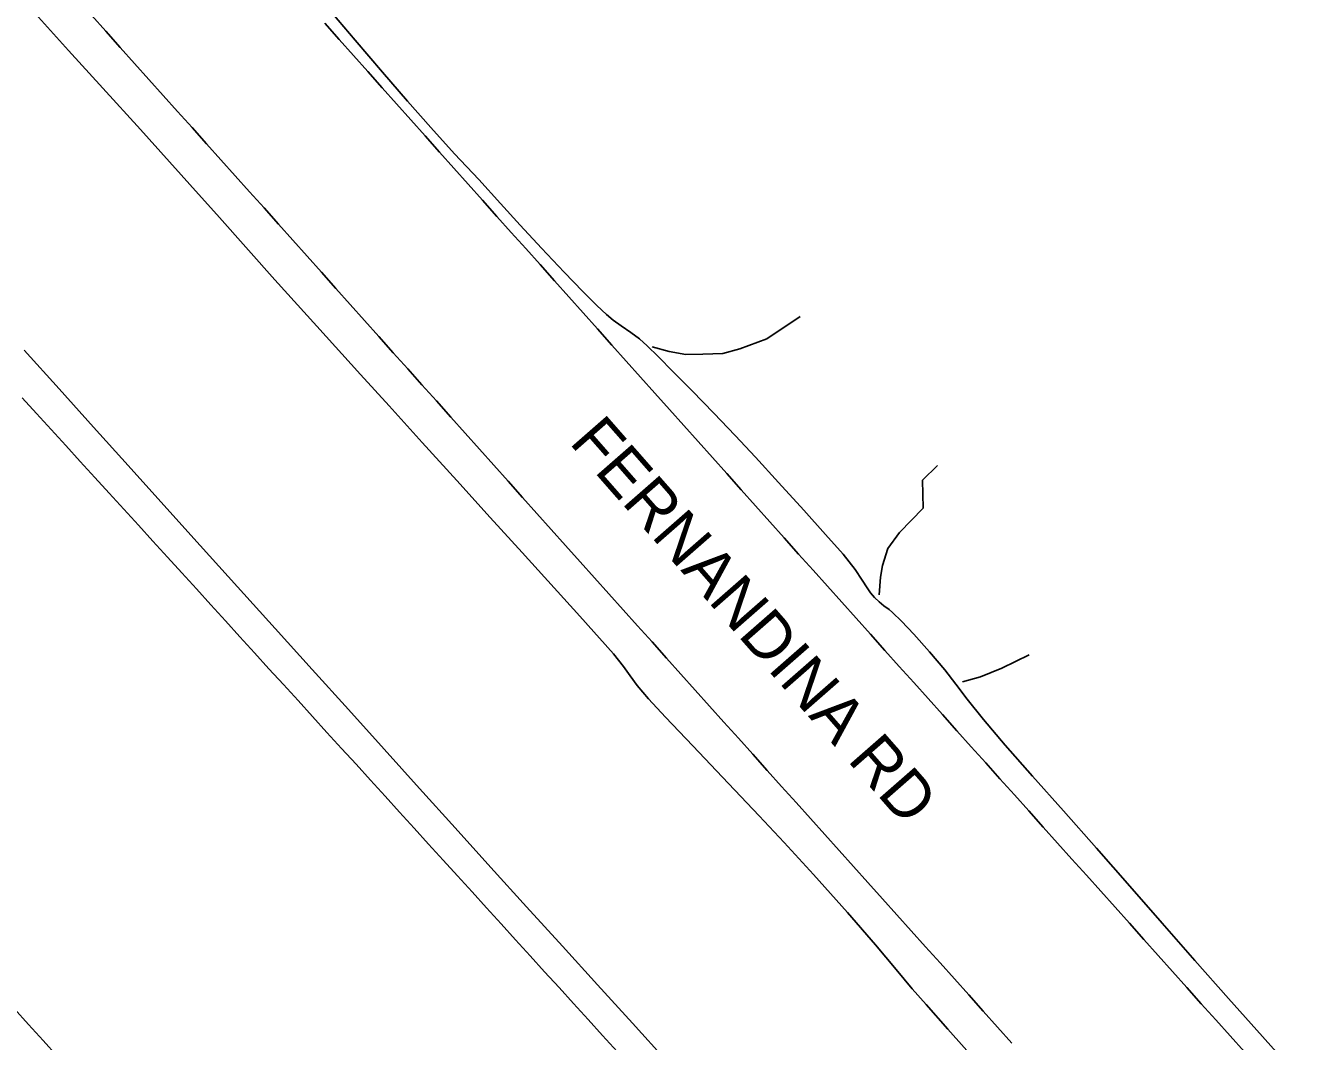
# Model space of a CAD drawing. Extents: x 1948091 to 1975253, y 787267 to 823306.
# Drawn here: x 1963119.6 to 1963266.8, y 805919.2 to 806037.1 of the extents above; entities that cross this region are included whole.
import ezdxf

# ---------------------------------------------------------------- set-up
doc = ezdxf.new("R2010")
doc.units = 0
for name, color, linetype in [('RD_EX_Pavement_Markings', 7, 'Continuous'), ('RD_EX_Road', 7, 'Continuous'), ('RD_TX_RoadID', 7, 'Continuous')]:
    doc.layers.add(name, color=color, linetype=linetype)

msp = doc.modelspace()

# ---------------------------------------------------------------- linework, layer by layer
at = {"layer": 'RD_EX_Pavement_Markings'}
for points in [[(1963233.94, 805919.03), (1963232.28, 805920.9), (1963230.62, 805922.76), (1963228.95, 805924.62), (1963227.28, 805926.48), (1963225.62, 805928.34), (1963223.95, 805930.2), (1963222.28, 805932.07), (1963220.61, 805933.93), (1963218.94, 805935.79), (1963217.27, 805937.65), (1963215.6, 805939.51), (1963213.93, 805941.37), (1963212.27, 805943.23), (1963210.6, 805945.09), (1963208.93, 805946.95), (1963207.26, 805948.81), (1963205.59, 805950.67), (1963203.92, 805952.54), (1963202.25, 805954.4), (1963200.58, 805956.26), (1963198.91, 805958.12), (1963197.25, 805959.98), (1963195.58, 805961.84), (1963193.91, 805963.7), (1963192.24, 805965.56), (1963190.57, 805967.42), (1963188.9, 805969.28), (1963187.23, 805971.14), (1963185.56, 805973.01), (1963183.9, 805974.87), (1963182.23, 805976.73), (1963180.57, 805978.6), (1963178.9, 805980.46), (1963177.24, 805982.33), (1963175.57, 805984.19), (1963173.91, 805986.06), (1963172.24, 805987.92), (1963170.58, 805989.79), (1963168.91, 805991.65), (1963167.25, 805993.52), (1963165.58, 805995.38), (1963163.92, 805997.24), (1963162.25, 805999.11), (1963160.59, 806000.97), (1963158.92, 806002.84), (1963157.26, 806004.7), (1963155.59, 806006.57), (1963153.93, 806008.43), (1963152.26, 806010.3), (1963150.6, 806012.16), (1963148.93, 806014.03), (1963147.27, 806015.89), (1963145.6, 806017.76), (1963143.93, 806019.62), (1963142.27, 806021.48), (1963140.6, 806023.34), (1963138.93, 806025.21), (1963137.26, 806027.07), (1963135.6, 806028.93), (1963133.93, 806030.79), (1963132.26, 806032.66), (1963130.59, 806034.52), (1963128.93, 806036.38), (1963127.26, 806038.24)], [(1963154.33, 806037.32), (1963155.98, 806035.45), (1963157.64, 806033.58), (1963159.29, 806031.71), (1963160.95, 806029.83), (1963162.61, 806027.97), (1963164.28, 806026.1), (1963165.94, 806024.24), (1963167.61, 806022.37), (1963169.27, 806020.51), (1963170.94, 806018.64), (1963172.6, 806016.78), (1963174.27, 806014.91), (1963175.93, 806013.05), (1963177.6, 806011.18), (1963179.26, 806009.32), (1963180.93, 806007.45), (1963182.59, 806005.59), (1963184.26, 806003.72), (1963185.92, 806001.86), (1963187.59, 806000), (1963189.25, 805998.13), (1963190.92, 805996.27), (1963192.58, 805994.4), (1963194.25, 805992.54), (1963195.91, 805990.67), (1963197.58, 805988.81), (1963199.24, 805986.95), (1963200.91, 805985.08), (1963202.57, 805983.22), (1963204.24, 805981.35), (1963205.9, 805979.49), (1963207.57, 805977.62), (1963209.23, 805975.76), (1963210.9, 805973.89), (1963212.56, 805972.03), (1963214.23, 805970.17), (1963215.9, 805968.31), (1963217.57, 805966.45), (1963219.23, 805964.58), (1963220.9, 805962.72), (1963222.57, 805960.86), (1963224.24, 805959), (1963225.9, 805957.14), (1963227.57, 805955.27), (1963229.24, 805953.41), (1963230.91, 805951.55), (1963232.57, 805949.69), (1963234.24, 805947.83), (1963235.91, 805945.97), (1963237.58, 805944.1), (1963239.24, 805942.24), (1963240.91, 805940.38), (1963242.58, 805938.52), (1963244.24, 805936.65), (1963245.91, 805934.79), (1963247.57, 805932.93), (1963249.24, 805931.06), (1963250.91, 805929.2), (1963252.57, 805927.34), (1963254.24, 805925.47), (1963255.9, 805923.61), (1963257.57, 805921.75), (1963259.23, 805919.88), (1963260.9, 805918.02)], [(1963119.24, 805993.89), (1963120.92, 805992.04), (1963122.61, 805990.2), (1963124.29, 805988.35), (1963125.97, 805986.5), (1963127.66, 805984.65), (1963129.34, 805982.8), (1963131.02, 805980.96), (1963132.71, 805979.11), (1963134.39, 805977.26), (1963136.07, 805975.41), (1963137.75, 805973.56), (1963139.44, 805971.71), (1963141.12, 805969.86), (1963142.8, 805968.01), (1963144.48, 805966.16), (1963146.16, 805964.31), (1963147.84, 805962.46), (1963149.53, 805960.62), (1963151.21, 805958.77), (1963152.89, 805956.92), (1963154.57, 805955.07), (1963156.25, 805953.22), (1963157.94, 805951.37), (1963159.62, 805949.52), (1963161.3, 805947.67), (1963162.98, 805945.82), (1963164.66, 805943.97), (1963166.34, 805942.12), (1963168.03, 805940.27), (1963169.71, 805938.42), (1963171.39, 805936.57), (1963173.07, 805934.73), (1963174.75, 805932.88), (1963176.43, 805931.02), (1963178.11, 805929.17), (1963179.79, 805927.32), (1963181.47, 805925.47), (1963183.15, 805923.62), (1963184.83, 805921.77), (1963186.51, 805919.92), (1963188.19, 805918.07)], [(1963118.31, 805923.07), (1963119.98, 805921.21), (1963121.66, 805919.36), (1963123.34, 805917.5)]]:
    msp.add_lwpolyline(points, dxfattribs=at)
at = {"layer": 'RD_EX_Road'}
for points in [[(1963266.83, 805915.53), (1963262.99, 805919.82), (1963259.06, 805924.22), (1963255.16, 805928.62), (1963251.38, 805932.94), (1963247.61, 805937.25), (1963243.74, 805941.65), (1963239.93, 805945.96), (1963236.33, 805950), (1963233.17, 805953.6), (1963230.66, 805956.58), (1963228.76, 805958.93), (1963227.45, 805960.67), (1963226.18, 805962.32), (1963224.39, 805964.41), (1963222.57, 805966.45), (1963221.16, 805967.96), (1963220.13, 805968.98), (1963219.72, 805969.32), (1963219.12, 805969.75), (1963218.56, 805970.2), (1963218.02, 805970.72), (1963217.56, 805971.26), (1963217.16, 805971.83), (1963216.6, 805972.71), (1963215.8, 805973.96), (1963214.39, 805975.73), (1963212.36, 805978.02), (1963209.82, 805980.84), (1963206.9, 805984.07), (1963204.23, 805986.98), (1963201.86, 805989.51), (1963199.41, 805992.08), (1963196.88, 805994.68), (1963194.69, 805996.9), (1963192.94, 805998.67), (1963191.66, 805999.92), (1963190.77, 806000.72), (1963189.79, 806001.47), (1963188.66, 806002.22), (1963187.74, 806002.88), (1963186.98, 806003.52), (1963185.85, 806004.6), (1963184.23, 806006.22), (1963182.07, 806008.45), (1963179.44, 806011.22), (1963176.97, 806013.89), (1963174.68, 806016.43), (1963172.15, 806019.19), (1963169.35, 806022.18), (1963166.6, 806025.21), (1963163.91, 806028.28), (1963160.99, 806031.66), (1963157.83, 806035.37), (1963154.54, 806039.22)], [(1963120.79, 806038.41), (1963124.61, 806034.15), (1963128.58, 806029.78), (1963132.96, 806024.98), (1963138.69, 806018.61), (1963142.11, 806014.77), (1963148.54, 806007.56), (1963153.39, 806002.19), (1963158.46, 805996.59), (1963161.77, 805992.93), (1963165.6, 805988.71), (1963169.6, 805984.28), (1963173.47, 805980.01), (1963177.19, 805975.92), (1963183.89, 805968.56), (1963187.78, 805964.18), (1963188.94, 805962.7), (1963189.69, 805961.63), (1963190.5, 805960.5), (1963191.83, 805958.96), (1963193.82, 805956.85), (1963196.97, 805953.52), (1963201.11, 805949.15), (1963204.66, 805945.39), (1963207.56, 805942.31), (1963210.97, 805938.58), (1963214.9, 805934.18), (1963218.13, 805930.45), (1963220.53, 805927.57), (1963222.41, 805925.35), (1963224.01, 805923.52), (1963226.53, 805920.67), (1963230.01, 805916.74)], [(1963209.4, 806003.32), (1963205.55, 806000.7), (1963202.43, 805999.55), (1963200.44, 805999), (1963198.14, 805998.93), (1963196.16, 805998.89), (1963194.21, 805999.26), (1963192.27, 805999.79)], [(1963193.97, 805916.95), (1963189.98, 805921.35), (1963185.93, 805925.79), (1963181.85, 805930.29), (1963177.71, 805934.84), (1963173.56, 805939.42), (1963169.43, 805943.99), (1963165.3, 805948.56), (1963161.19, 805953.11), (1963157.05, 805957.71), (1963152.84, 805962.38), (1963148.56, 805967.12), (1963144.21, 805971.94), (1963139.88, 805976.74), (1963135.66, 805981.43), (1963131.53, 805986.01), (1963127.52, 805990.47), (1963123.52, 805994.91), (1963119.48, 805999.39)], [(1963225.31, 805986.03), (1963223.6, 805984.33), (1963223.67, 805981.08), (1963220.94, 805978.27), (1963219.58, 805976.41), (1963218.94, 805974.43), (1963218.71, 805973.06), (1963218.56, 805971.01)], [(1963228.23, 805960.92), (1963230.3, 805961.5), (1963232.77, 805962.51), (1963235.94, 805964.06)]]:
    msp.add_lwpolyline(points, dxfattribs=at)

# ---------------------------------------------------------------- texts
at = {"layer": 'RD_TX_RoadID'}
msp.add_text('FERNANDINA RD', height=5.4, rotation=311.2042, dxfattribs=at).set_placement((1963182.54, 805988.67))

doc.saveas('drawing.dxf')
